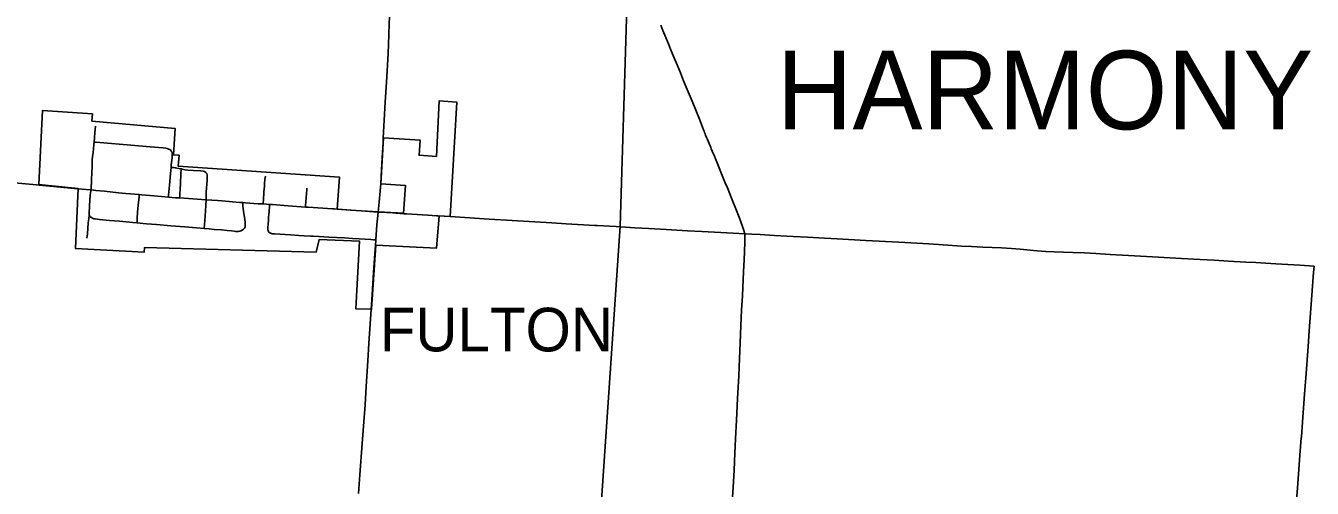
# Model space of a CAD drawing. Extents: x 1815539 to 1947826, y 273303 to 993194.
# Drawn here: x 1874888 to 1889640, y 894018 to 899320 of the extents above; entities that cross this region are included whole.
import ezdxf

# ---------------------------------------------------------------- set-up
doc = ezdxf.new("R2010")
doc.units = 0
for name, color, linetype in [('GM_X_City_Street', 7, 'Continuous'), ('GM_X_Corporation', 7, 'Continuous'), ('GM_X_Corporation_Text', 7, 'Continuous'), ('GM_X_County_Road', 7, 'Continuous'), ('GM_X_State_Route', 7, 'Continuous'), ('GM_X_Township', 7, 'Continuous'), ('GM_X_Township_Road', 7, 'Continuous'), ('GM_X_Township_Text', 7, 'Continuous')]:
    doc.layers.add(name, color=color, linetype=linetype)

msp = doc.modelspace()

# ---------------------------------------------------------------- linework, layer by layer
at = {"layer": 'GM_X_City_Street'}
for points in [[(1875671, 897987), (1875675, 898035), (1875681, 898097), (1875688, 898169)], [(1875637, 897437), (1875638, 897457), (1875641, 897538), (1875642, 897571), (1875644, 897620), (1875648, 897718), (1875651, 897784), (1875654, 897817), (1875659, 897865), (1875665, 897913), (1875669, 897960), (1875671, 897987)], [(1875671, 897987), (1875696, 897985), (1875826, 897975), (1876005, 897958), (1876315, 897931), (1876462, 897919), (1876494, 897915), (1876510, 897912), (1876526, 897907), (1876541, 897900), (1876546, 897896), (1876551, 897891)], [(1876568, 897837), (1876568, 897823), (1876566, 897807), (1876562, 897778), (1876557, 897726), (1876554, 897695)], [(1876554, 897695), (1876547, 897626), (1876535, 897494), (1876526, 897378), (1876524, 897355)], [(1876554, 897695), (1876568, 897695), (1876587, 897695), (1876603, 897693), (1876619, 897689), (1876669, 897678)], [(1876652, 897346), (1876654, 897370), (1876655, 897386), (1876660, 897453), (1876664, 897503), (1876668, 897635), (1876669, 897666), (1876669, 897678)], [(1876669, 897678), (1876682, 897675), (1876714, 897669), (1876746, 897665), (1876810, 897660), (1876891, 897657), (1876923, 897654), (1876938, 897650), (1876954, 897638)], [(1876955, 897326), (1876957, 897415), (1876967, 897545), (1876969, 897593), (1876968, 897609), (1876964, 897625), (1876954, 897638)], [(1877611, 897277), (1877611, 897292), (1877613, 897318), (1877619, 897416), (1877624, 897482), (1877626, 897515), (1877631, 897554), (1877634, 897579), (1877637, 897594)], [(1875487, 897451), (1875579, 897442), (1875637, 897437)], [(1875615, 897147), (1875614, 897176), (1875621, 897323), (1875626, 897373), (1875631, 897405), (1875637, 897437)], [(1875637, 897437), (1875692, 897432), (1875789, 897422), (1875953, 897404), (1876035, 897397), (1876133, 897389), (1876190, 897384)], [(1878095, 897241), (1878096, 897259), (1878102, 897346), (1878106, 897395), (1878111, 897442), (1878112, 897457)], [(1876163, 897059), (1876164, 897078), (1876165, 897111), (1876170, 897184), (1876177, 897263), (1876188, 897358), (1876190, 897384)], [(1876190, 897384), (1876214, 897382), (1876312, 897373), (1876443, 897361), (1876524, 897355)], [(1876524, 897355), (1876606, 897349), (1876652, 897346)], [(1876652, 897346), (1876754, 897339), (1876852, 897331), (1876955, 897326)], [(1876934, 896997), (1876940, 897089), (1876948, 897193), (1876953, 897262), (1876955, 897326)], [(1876955, 897326), (1877086, 897315), (1877138, 897311), (1877344, 897295), (1877378, 897293)], [(1877385, 896989), (1877395, 897001), (1877402, 897016), (1877405, 897032), (1877405, 897049), (1877404, 897065), (1877400, 897098), (1877383, 897196), (1877379, 897225), (1877377, 897246), (1877377, 897279), (1877378, 897293)], [(1877378, 897293), (1877408, 897290), (1877554, 897280), (1877611, 897277)], [(1877611, 897277), (1877682, 897272)], [(1877686, 896947), (1877677, 896954), (1877671, 896963), (1877667, 896971), (1877665, 896978), (1877663, 896994), (1877663, 897011), (1877667, 897043), (1877671, 897092), (1877673, 897125), (1877675, 897158), (1877678, 897191), (1877681, 897250), (1877682, 897272)], [(1877682, 897272), (1877717, 897270), (1877897, 897256), (1877995, 897248), (1878095, 897241)], [(1875588, 896886), (1875594, 896935), (1875605, 897059), (1875610, 897108), (1875615, 897147)], [(1875615, 897147), (1875621, 897138), (1875627, 897130), (1875634, 897125), (1875643, 897120), (1875655, 897113), (1875670, 897108), (1875686, 897105), (1875735, 897098), (1875849, 897088), (1875963, 897078), (1876114, 897063), (1876163, 897059)], [(1878095, 897241), (1878126, 897239), (1878405, 897221), (1878425, 897220)], [(1879223, 897165), (1879255, 897163), (1879499, 897148), (1879597, 897141), (1879613, 897141)], [(1876163, 897059), (1876273, 897049), (1876387, 897041), (1876550, 897028), (1876713, 897015), (1876844, 897004), (1876934, 896997)], [(1876934, 896997), (1876992, 896991), (1877049, 896986), (1877131, 896980), (1877197, 896973), (1877246, 896968), (1877278, 896965), (1877294, 896963), (1877310, 896963), (1877326, 896963), (1877341, 896964), (1877355, 896969), (1877369, 896976), (1877385, 896989)], [(1877686, 896947), (1877693, 896943), (1877699, 896940), (1877707, 896937), (1877715, 896936), (1877740, 896934), (1877801, 896931), (1877924, 896922), (1878018, 896916), (1878082, 896912), (1878154, 896909), (1878184, 896907), (1878249, 896904), (1878363, 896898), (1878542, 896888), (1878636, 896881), (1878711, 896876), (1878779, 896872), (1878845, 896868), (1878877, 896867), (1878902, 896866)]]:
    msp.add_lwpolyline(points, dxfattribs=at)
at = {"layer": 'GM_X_Corporation'}
msp.add_lwpolyline([(1875647, 898225), (1876603, 898141), (1876581, 897839), (1876646, 897838), (1876637, 897710), (1878484, 897585), (1878460, 897219), (1878613, 897206), (1878930, 897186), (1879221, 897171), (1879244, 897487), (1878959, 897508), (1878990, 898034), (1879410, 898009), (1879398, 897835), (1879597, 897822), (1879630, 898461), (1879830, 898445), (1879753, 897133), (1879629, 897141), (1879598, 896771), (1878904, 896804), (1878854, 896070), (1878672, 896076), (1878714, 896851), (1878252, 896869), (1878219, 896726), (1876250, 896779), (1876247, 896726), (1875458, 896768), (1875487, 897456), (1875039, 897500), (1875079, 898348), (1875653, 898309)], close=True, dxfattribs=at)
at = {"layer": 'GM_X_County_Road'}
for points in [[(1873637, 897625), (1873803, 897609), (1874064, 897585), (1874423, 897551), (1874652, 897529), (1874799, 897515), (1875011, 897497), (1875043, 897494)], [(1875043, 897494), (1875165, 897481), (1875445, 897455), (1875487, 897451)], [(1878425, 897220), (1878620, 897206), (1878734, 897197), (1878881, 897186), (1878928, 897183)], [(1878928, 897183), (1878962, 897181), (1879092, 897174), (1879223, 897165)], [(1879613, 897141), (1879754, 897132)], [(1879754, 897132), (1880202, 897104), (1880464, 897088), (1880922, 897061), (1881086, 897051), (1881413, 897031), (1881441, 897030)], [(1881441, 897030), (1881659, 897019), (1881871, 897004), (1882034, 896996), (1882230, 896984), (1882476, 896970), (1882640, 896962), (1882787, 896953), (1883000, 896941), (1883134, 896934)], [(1882984, 893800), (1882998, 894029), (1883010, 894225), (1883020, 894422), (1883028, 894586), (1883038, 894799), (1883051, 895045), (1883063, 895307), (1883072, 895504), (1883080, 895684), (1883088, 895881), (1883097, 896061), (1883105, 896225), (1883118, 896504), (1883124, 896635), (1883132, 896832), (1883134, 896897), (1883134, 896934)], [(1883134, 896934), (1883213, 896930), (1883311, 896926), (1883475, 896917), (1883687, 896905), (1883851, 896895), (1884047, 896884), (1884194, 896876), (1884522, 896858), (1884899, 896839), (1885243, 896818), (1885406, 896807), (1885619, 896795), (1885734, 896788), (1885864, 896781), (1886078, 896774), (1886192, 896768), (1886291, 896760), (1886405, 896747), (1886486, 896739), (1886584, 896732), (1886682, 896728), (1886896, 896722), (1887027, 896716), (1887158, 896709), (1887321, 896699), (1887534, 896687), (1887878, 896667), (1888140, 896652), (1888353, 896640), (1888517, 896632), (1888681, 896622), (1888877, 896611), (1888992, 896604), (1889221, 896591), (1889499, 896575), (1889661, 896565)], [(1889515, 894607), (1889527, 894775), (1889552, 895102), (1889565, 895282), (1889592, 895642), (1889606, 895822), (1889636, 896230), (1889655, 896492), (1889661, 896565)], [(1889363, 892553), (1889369, 892649), (1889379, 892780), (1889393, 892976), (1889407, 893172), (1889419, 893319), (1889431, 893483), (1889432, 893498), (1889441, 893615), (1889443, 893646), (1889456, 893826), (1889474, 894072), (1889499, 894399), (1889514, 894595), (1889515, 894607)]]:
    msp.add_lwpolyline(points, dxfattribs=at)
at = {"layer": 'GM_X_State_Route'}
for points in [[(1878988, 898033), (1879010, 898444), (1879024, 898673), (1879042, 899001), (1879050, 899214), (1879055, 899345), (1879062, 899493), (1879072, 899673), (1879083, 899919), (1879099, 900263), (1879107, 900460), (1879124, 900787), (1879127, 900836), (1879141, 901098), (1879156, 901426), (1879168, 901655), (1879188, 902032), (1879203, 902327), (1879220, 902671), (1879245, 903138)], [(1878982, 897927), (1878985, 897969), (1878988, 898033)], [(1878959, 897509), (1878964, 897593), (1878972, 897740), (1878982, 897927)], [(1878928, 897183), (1878941, 897298), (1878953, 897429), (1878959, 897509)], [(1878897, 896806), (1878901, 896859), (1878902, 896866), (1878914, 897039), (1878928, 897183)], [(1878849, 896071), (1878852, 896118), (1878877, 896492), (1878887, 896655), (1878897, 896806)], [(1878704, 893959), (1878720, 894172), (1878746, 894531), (1878759, 894728), (1878778, 894973), (1878791, 895186), (1878810, 895480), (1878822, 895676), (1878849, 896071)]]:
    msp.add_lwpolyline(points, dxfattribs=at)
at = {"layer": 'GM_X_Township'}
msp.add_lwpolyline([(1880714, 883463), (1880836, 885744), (1880863, 886256), (1881338, 891636), (1881703, 897023), (1881803, 900282), (1881806, 900375), (1881918, 903829), (1881985, 905459), (1882074, 908232), (1882082, 908847), (1882260, 912507), (1887758, 913255), (1888309, 913332)], dxfattribs=at)
at = {"layer": 'GM_X_Township_Road'}
for points in [[(1883134, 896934), (1883123, 896973), (1883108, 897017), (1883068, 897125), (1883038, 897202), (1882989, 897323), (1882934, 897460), (1882909, 897520), (1882890, 897565), (1882860, 897641), (1882848, 897672), (1882816, 897747), (1882796, 897794), (1882784, 897825), (1882760, 897883), (1882749, 897910), (1882744, 897923), (1882739, 897934), (1882736, 897943), (1882724, 897970), (1882715, 897991), (1882705, 898014), (1882695, 898040), (1882683, 898067), (1882677, 898082), (1882672, 898097), (1882666, 898112), (1882660, 898127), (1882648, 898157), (1882636, 898188), (1882624, 898218), (1882612, 898248), (1882571, 898351), (1882529, 898454), (1882462, 898615), (1882432, 898689), (1882420, 898719), (1882407, 898749), (1882395, 898779), (1882358, 898870), (1882320, 898961), (1882282, 899052), (1882257, 899112), (1882194, 899265), (1882170, 899326)], [(1876551, 897891), (1876557, 897884), (1876563, 897876), (1876566, 897868), (1876568, 897856), (1876568, 897839), (1876568, 897837)]]:
    msp.add_lwpolyline(points, dxfattribs=at)

# ---------------------------------------------------------------- texts
at = {"layer": 'GM_X_Corporation_Text'}
msp.add_text('FULTON', height=500, rotation=0, dxfattribs=at).set_placement((1878947, 895587))
at = {"layer": 'GM_X_Township_Text'}
msp.add_text('HARMONY', height=900, rotation=0, dxfattribs=at).set_placement((1883499, 898133))

doc.saveas('drawing.dxf')
